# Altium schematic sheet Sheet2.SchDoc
size A; SheetNumber: 1; SheetTotal: 1
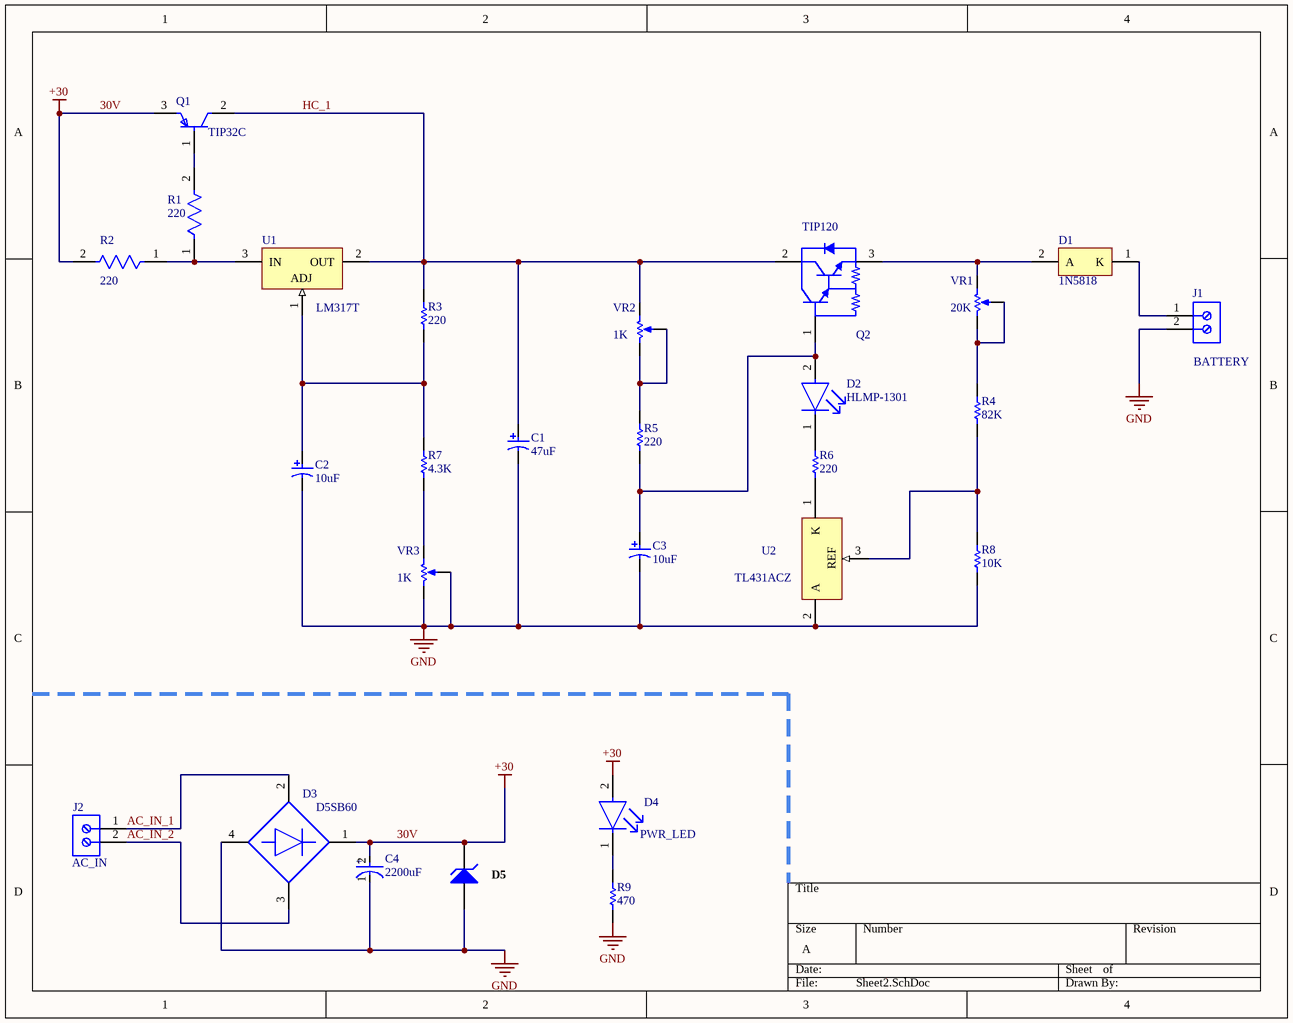
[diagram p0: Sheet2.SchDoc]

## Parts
C1  47uF  [CAPPR55-200-1100X500X1200]
C2  10uF  [CAPPR55-200-1100X500X1200]
C3  10uF  [CAPPR55-200-1100X500X1200]
C4  2200uF  [FP-RAD-TH-D_12_5_0_5-L_40-MFG]
D1  1N5818  [ONSC-AXIAL_LEAD-2-59-10_P]
D2  HLMP-1301  [FP-HLMP-1301-MFG]
D3  D5SB60  [FP-GBU-MFG]
D4  PWR_LED  [FP-HLMP-1503-MFG]
D5  1N4732A  [FAIR-DO-41-2_V]  (value not drawn)
J1  BATTERY  [PHOE-1714955_V]
J2  AC_IN  [PHOE-1714955_V]
Q1  TIP32C  [FP-TO-220-P0A0015988-MFG]
Q2  TIP120  [ONSC-TO-220-3-221A-09]
R1  220  [FP-SP3A-MFG]
R2  220  [FP-SP3A-MFG]
R3  220  [RESA60-630X240]
R4  82K  [RESA60-630X240]
R5  220  [RESA60-630X240]
R6  220  [RESA60-630X240]
R7  4.3K  [RESA60-630X240]
R8  10K  [RESA60-630X240]
R9  470  [RESA60-630X240]
U1  LM317T  [TO-220]
U2  TL431ACZ  [TO-92]
VR1  20K  [BOUR-3852A-282-103AL-3_V]
VR2  1K  [BOUR-3852A-282-103AL-3_V]
VR3  1K  [BOUR-3852A-282-103AL-3_V]

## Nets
30V: C4.2(A) D3.1(+) D4.2(A) D5.2(K) Q1.3(E) R2.2  [also labelled +30]
GND: C1.2 C2.2 C3.2 C4.1(C) D3.4(-) D5.1(A) J1.2 R8.1 R9.1 U2.2(A) VR3.2(S) VR3.3(CW)
AC_IN_1: D3.2(1_~) J2.1
AC_IN_2: D3.3(2_~) J2.2
HC_1: C1.1 Q1.2(C) Q2.2(C) R3.2 U1.2(OUT) VR2.1(CCW)
NetC2_1: C2.1 R3.1 R7.2 U1.1(ADJ)
NetC3_1: C3.1 D2.2(A) Q2.1(B) R5.1
NetD1_1: D1.1(K) J1.1
NetD1_2: D1.2(A) Q2.3(E) VR1.1(CCW)
NetD2_1: D2.1(C) R6.2
NetD4_1: D4.1(C) R9.2
NetQ1_1: Q1.1(B) R1.2
NetR1_1: R1.1 R2.1 U1.3(IN)
NetR4_1: R4.1 R8.2 U2.3(REF)
NetR4_2: R4.2 VR1.2(S) VR1.3(CW)
NetR5_2: R5.2 VR2.2(S) VR2.3(CW)
NetR6_1: R6.1 U2.1(K)
NetR7_1: R7.1 VR3.1(CCW)

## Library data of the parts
C1 = CMP-1665-00038-2: Aluminum Electrolytic Capacitor, 10 uF, +/- 20%, 50 V, -40 to 85 degC, 2-Pin THD, RoHS, Bulk; Manufacturer: Panasonic; Life (Hours): 2000Hour; Lead/Base Style: Straight; Dissipation Factor: 0.12%; Capacitance: 10uF; Leakage Current: 3uA; Dielectric Material: Aluminium; Lead Diameter: 0.5mm; Voltage Rating: 50V; Ripple Current: 65mA
C2 C3 = CMP-1665-00038-2: Aluminum Electrolytic Capacitor, 10 uF, +/- 20%, 50 V, -40 to 85 degC, 2-Pin THD, RoHS, Bulk; Manufacturer: Panasonic; Life (Hours): 2000Hour; Lead/Base Style: Straight; Dissipation Factor: 0.12%; Leakage Current: 3uA; Dielectric Material: Aluminium; Lead Diameter: 0.5mm; Voltage Rating: 50V; Ripple Current: 65mA
C4 = CMP-05427-000828-1: Aluminum Electrolytic Capacitors (Radial Lead Type) AEC-Q200 Qualified 2200uF ±20% 35V; Impedance: 14mR; Ripple Current: 3.01A; Life (Hours): 5000Hour; Lead Diameter: 0.8mm; Capacitance: 2.2mF; Dielectric Material: Aluminium
D1 = CMP-1055-00034-1: Rectifier, 2-Pin Axial_Lead, Pb-Free, Bulk Bag; Manufacturer: On Semiconductor; IFSM Max (A): 25; Note1: 0; Configuration: Single
D2 = CMP-18399-000007-1: LED RED DIFFUSED T-1 T/H; Manufacturer: Broadcom; Forward Current: 10mA; Max Junction Temp: +110°C; Wavelength: 626nm; Led Orientation: Straight; Viewing Angle: 60°; Luminous Intensity: 3.4mcd; Forward Voltage: 1.9V; Reverse Voltage: 5V; Peak Emmision Wavelength: 635nm
D3 = CMP-02540-000020-1: BRIDGE RECT 1PHASE 800V 3.9A GBU; Manufacturer: Vishay; Manufacturer Part Number: GBU8K-E3/45; Peak Reverse Current: 5uA; Max Junction Temp: +150°C; Standoff Height: 1.52mm; Capacitance: 68pF; Max Surge Forward Current: 200A; Value: 68pF
D4 = CMP-18399-000010-1: LED GREEN DIFFUSED T-1 T/H; Manufacturer: Broadcom; Reverse Voltage: 5V; Wavelength: 569nm; Forward Voltage: 2.1V; Led Orientation: Straight; Viewing Angle: 60°; Max Junction Temp: +110°C; Peak Emmision Wavelength: 565nm; Luminous Intensity: 1mcd; Standoff Height: 0.88mm; Forward Current: 10mA
D5 = CMP-0892-00030-1: Zener Diode, 4.7V, 1W, 5%, -65 to 200 degC, 2-Pin DO-41, Body 2.72 x 5.2 mm, RoHS; Manufacturer: Fairchild Semiconductor; VZ (Min.) (V): 4.465; ZZ (Max) (ohm): 8; VZ (Max.) (V): 4.935; PD (W): 1; IR (uA): 10; Test Current IZ (mA): 53
J1 J2 = CMP-2000-05797-1: PC Terminal Block, Pitch 6.35 mm, 1 x 2 Position, Height 21.5 mm, Tail Lenght 5.1 mm, RoHS, Bulk; Manufacturer: Phoenix Contact
Q1 = CMP-12195-000005-1: TRANS PNP 100V 3A TO-220; Manufacturer: STMicroelectronics; Standoff Height: 3.5mm; Number Of Pnp: 1; Max Collector Current: -3A; Emitter Base Voltage: -5V; Collector Emitter Voltage: -100V; Hfe Testvce: -4V; Hfe Max: 50; Collector Emitter Saturation Voltage: -1.2V; Power Dissipation: 2W; Max Junction Temp: +150°C; Hfe Min: 10
Q2 = CMP-1047-00140-1: Plastic Medium-Power, Complementary Silicon Transistor, 3-Pin TO-220, Tube; Manufacturer: On Semiconductor; IC Continuous (A): 5; Polarity: NPN
R1 R2 = CMP-26528-000004-1: RES 10 OHM 5% 4W AXIAL; Resistance: 10R; Temperature Coefficient: 20ppm/°C
R3-R9 = CMP-1659-00075-1: Axial Resistor, 1 KOhm, +/- 1%, 250 mW, -55 to 155 degC, 2-Pin THD, RoHS, Bulk; Voltage Rating: 250 V; Resistance: 10 kohm; Power Rating: 250 mW
U1 = CMP-0244-00444-1: 1.5A, 1.2V to 37V Adjustable Voltage Regulator, 3-Pin TO-220
U2 = CMP-0242-00006-1: Programmable Voltage Reference, 2.5 to 36V, 3-Pin TO-92
VR1-VR3 = CMP-2000-05079-1: Diameter Panel Control, 10 KOhm, +/- 10%, 2 W, -1 to 125 degC, 3-Pin THD, RoHS, Bulk; Manufacturer: Bourns; Temperature Coefficient: ±150ppm/degC; Number of Gangs: 1; Other Names: 3852A282103AL; Actuator Length: 0.875"(22.23mm); Resistive Material: Cermet; PCN Design/Specification: PBTResinJun/2011; Rotation: 280deg; PCN Other: MultipleChanges01/Dec/2012; Catalog Drawings: 3852SeriesSide1 / 3852SeriesSide2; Online Catalog: 3852and3856Series; Associated Product: 36-8560-ND / -KNOBINSTRUMW/DIALRND.9"DIA / 36-8555-ND / -KNOBINSTRUMSKIRTEDRND.7"DIA / 36-8556-ND / -KNOBINSTRUMSKIRTEDRND.9"DIA / 36-8565-ND / -KNOBINSTRUMDBLBARRND.7"DIA / 36-8566-ND / -KNOBINSTRUMDBLBARRND.9"DIA / 36-8568-ND / -KNOBINSTRUMSGLBARRND.7"DIA / 36-8569-ND / -KNOBINSTRUMSGLBARRND.9"DIA / 36-8559-ND / -KNOBINSTRUMW/DIALRND.7"DIA / 226-1006-ND / -KNOBBLKGLOSS.75"DIA.250"SHAFT / 226-1007-ND / -KNOBBLKGLOSS.925"DIA.250"SHAFT / 226-1011-ND / -KNOBBLKGLOS; Actuator Diameter: 0.250"(6.35mm); Built in Switch: None; Resistance (Ohms): 10k; Power (Watts): 2W; Actuator Type: Slotted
